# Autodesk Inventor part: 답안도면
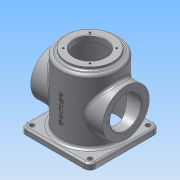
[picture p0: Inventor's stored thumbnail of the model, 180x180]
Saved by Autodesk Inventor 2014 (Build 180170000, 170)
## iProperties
Created: 2015-10
Part Number: 답안도면
Material: 알루미늄 6061
Document SubType Name: Modeling
Designer: net
Density: 2.71 g/cm^3
Appearance: 알루미늄 - 평지
Mass: 954.135 g
Surface Area: 1042.2 cm^2
Volume: 352.079 cm^3
Author: net
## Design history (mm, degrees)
sketch "스케치1"
  geometry: 1 further point
sketch "스케치2"
  geometry: L1 (60, 60)-(-60, 60); L2 (-60, 60)-(-60, -60); L3 (-60, -60)-(60, -60); L4 (60, -60)-(60, 60); L5 (60, 60)-(-60, -60); L6 (-60, 60)-(60, -60); 1 further point
  constraints: 12 end point, 2 midpoint, 2 parallel, 1 horizontal, 1 perpendicular
  dimensions: "d0" = 120 distance of L3.end L2.end; "d1" = 120 distance between parallel lines of L3 L1
extrude "돌출1" new body sketch "스케치2" distance "d2" = 10; taper "d3" = 0 deg
sketch "스케치4"
  geometry: L1 (-60, 0)-(60, 0) reference; L2 (-60, 0)-(-60, 10) reference; L3 (60, 0)-(60, 10) reference; L4 (-60, 10)-(60, 10) reference; L5 (0, 0)-(0, 120); L6 (0, 120)-(-50, 120); L7 (-50, 120)-(-50, 0); L8 (-45, 0)-(-45, 115); L9 (-45, 115)-(0, 115); L10 (-45, 0)-(0, 0); 1 further point
  constraints: 12 end point, 3 point on line, 2 horizontal, 2 midpoint, 1 parallel, 1 vertical
  dimensions: "d10" = 50 distance between parallel lines of L5 L7; "d11" = 5 distance between parallel lines of L8 L7; "d16" = 120 distance between parallel lines of L1 L6; "d17" = 5 distance between parallel lines of L9 L6; "d18" = 10 distance from line of L8.start L4
revolve "회전2" stored, may be unused: angle "d19" = 90 deg
revolve "회전3" stored, may be unused: angle "d20" = 90 deg
sketch "스케치5"
  geometry: C1 r 40 at (0, 0); C2 r 27 at (0, 0); C3 r 50 at (0, 0) reference; C4 r 27 at (0, 0); 1 further point
  constraints: 3 centre point, 3 coincident, 1 concentric
  dimensions: "d21" = 80 diameter of C1; "d22" = 54 diameter of C2
extrude "돌출2" join sketch "스케치5" distance "d23" = 5; taper "d24" = 0 deg
node "작업 평면2"
sketch "스케치8"
  geometry: L1 (50, 120)-(-50, 120) reference; L2 (-50, 10)-(50, 10) reference; L3 (-60, 0)-(60, 0) reference; L4 (-60, 0)-(60, 0) reference; L5 (60, 0)-(60, 10) reference; L6 (-60, 10)-(60, 10) reference; L7 (-60, 0)-(-60, 10) reference; C1 r 40 at (0, 60); C2 r 27 at (0, 60); 2 further points
  constraints: 2 centre point, 1 coincident, 1 midpoint, 1 vertical alignment
  dimensions: "d51" = 80 diameter of C1; "d52" = 54 diameter of C2; "d53" = 60 distance of point (0, 0) C1.centre
  node "투영된 루프3"
  node "투영된 루프4"
extrude "돌출6" join sketch "스케치8" stored distance "d54" = 5; taper "d55" = 0 deg
extrude "돌출7" cut sketch "스케치8" stored distance "d56" = 5; taper "d57" = 0 deg
sketch "스케치9"
  geometry: C1 r 27 at (0, 0) reference; C2 r 27 at (0, 0)
  constraints: 1 centre point, 1 coincident
  dimensions: "d58" = 54 diameter of C2
extrude "돌출8" cut sketch "스케치9" stored distance "d59" = 5; taper "d60" = 0 deg
sketch "스케치10"
  geometry: C1 r 27 at (0, 0) reference; 2 further points
  constraints: 1 horizontal alignment
  dimensions: "d61" = 45 deg dimension on C1.centre point (22.981, -22.981) point (33.702, 0); "d62" = 32.5 distance of C1.centre point (22.981, -22.981)
hole "구멍2" sketch "스케치10" at (22.981, -22.981) diameter "d63" = 3.242; stored, may be unused: countersink angle "d67" = 90 deg, drill point angle "d69" = 118 deg; dims "d64" = 8, "d65" = 4, "d66" = 2, "d68" = 10
sketch "스케치11"
  geometry: C1 r 27 at (0, 0) reference; 2 further points
  constraints: 1 horizontal alignment
  dimensions: "d73" = 32.5 distance of C1.centre point (-32.5, 0)
hole "구멍3" sketch "스케치11" at (-32.5, 0) diameter "d74" = 3.242; stored, may be unused: countersink angle "d78" = 90 deg, drill point angle "d80" = 118 deg; dims "d75" = 8, "d76" = 4, "d77" = 2, "d79" = 10
hole "구멍4" diameter "d86" = 8; stored, may be unused: countersink angle "d90" = 90 deg, drill point angle "d92" = 0 deg; dims "d84" = 10, "d85" = 10, "d87" = 8, "d88" = 4, "d89" = 2, "d91" = 10
fillet "모깎기1" dims "d99" = 10
fillet "모깎기2" dims "d100" = 5
fillet "모깎기3" dims "d101" = 5
fillet "모깎기4" dims "d102" = 5
fillet "모깎기5" dims "d103" = 5
fillet "모깎기6" dims "d104" = 3
fillet "모깎기7" dims "d105" = 3
chamfer "모따기1" distance "d106" = 3; stored, may be unused: second distance "d107" = 2, angle "d108" = 45 deg
chamfer "모따기2" distance "d109" = 1; stored, may be unused: second distance "d110" = 2, angle "d111" = 45 deg
chamfer "모따기3" distance "d112" = 1; stored, may be unused: second distance "d113" = 2, angle "d114" = 45 deg
node "작업 평면3"
sketch "스케치12"
  geometry: L1 (-48, -60)-(48, -60) reference; L2 (-62, 40)-(-62, -40) reference; 2 further points
  constraints: 1 other
feature "엠보싱1" sketch "스케치12" dims "d0" = 120, "d1" = 120, "d115" = 0.5, "d116" = 0
node "작업 평면1"
sketch "스케치6"
  geometry: L1 (50, 120)-(-50, 120) reference; L2 (-50, 10)-(50, 10) reference; C1 r 40 at (0, 60); C2 r 27 at (0, 60); 1 further point
  constraints: 2 centre point, 1 coincident, 1 vertical alignment
  dimensions: "d26" = 80 diameter of C1; "d27" = 54 diameter of C2; "d28" = 60 distance of point (0, 0) C1.centre
  node "투영된 루프2"
extrude "돌출3" join sketch "스케치6" stored distance "d29" = 5; taper "d30" = 0 deg
extrude "돌출4" cut sketch "스케치6" stored distance "d31" = 5; taper "d32" = 0 deg
extrude "돌출5" cut sketch "스케치5" stored distance "d33" = 5; taper "d34" = 0 deg
hole "구멍1" diameter "d37" = 8; stored, may be unused: countersink angle "d41" = 90 deg, drill point angle "d43" = 0 deg; dims "d35" = 10, "d36" = 10, "d38" = 6, "d39" = 4, "d40" = 2, "d42" = 8
sketch "스케치7"
  geometry: C1 r 27 at (0, 0) reference; C2 r 40 at (0, 0) reference
node "솔리드1"
mirror "대칭4"
pattern_circular "원형 패턴1" dims angle "d71" = 360 deg
pattern_circular "원형 패턴2" dims angle "d82" = 360 deg
mirror "대칭5"
pattern_linear "직사각형 패턴2" dims "d95" = 100
mirror "대칭3"
pattern_linear "직사각형 패턴1" dims "d46" = 100
mirror "대칭1"
mirror "대칭2"
other parameters: "d25" = 62.5, "d50" = 62
